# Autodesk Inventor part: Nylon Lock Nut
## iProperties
Category: Fasteners
Title: Nylon Lock Nut
Author: QBZ
Shininess: 60.0
PropertySet Name: _Private Model Information
Created: 2001-04
Part Number: Nylock Nut
Document SubType Name: Modeling
Designer: QBZ
Description: 3/8 Std NC Nylock Nut
Material: Steel, Mild
Control State: 0
Master: False
Checked Out: False
PropertySet Name: Design Tracking Control
Density: 7.859999999999999
Volumn: 40.07686313737254
Area: 115.62685411210367
PropertySet Name: Model Information
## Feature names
1. Extrusion1
2. Revolution1
3. Extrusion2
4. Revolution2
